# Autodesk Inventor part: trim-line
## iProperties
Shininess: 64.0
Length Units: 11269
Angle Units: 11279
Time Units: 11290
Mass Units: 11283
Length Display Precision: 3
Angle Display Precision: 2
Compacted: True
Part Number: trim-line
Document SubType Name: Modeling
Created: 2003-08
Designer: Owner
Manufacturer: Standard
Standards Organization: Custom
Density: 1 g/cm^3
Density: 0.0
Volumn: 0.0
Area: 0.0
PropertySet Name: Model Information
Control State: 0
Master: False
Checked Out: False
Author: Owner
